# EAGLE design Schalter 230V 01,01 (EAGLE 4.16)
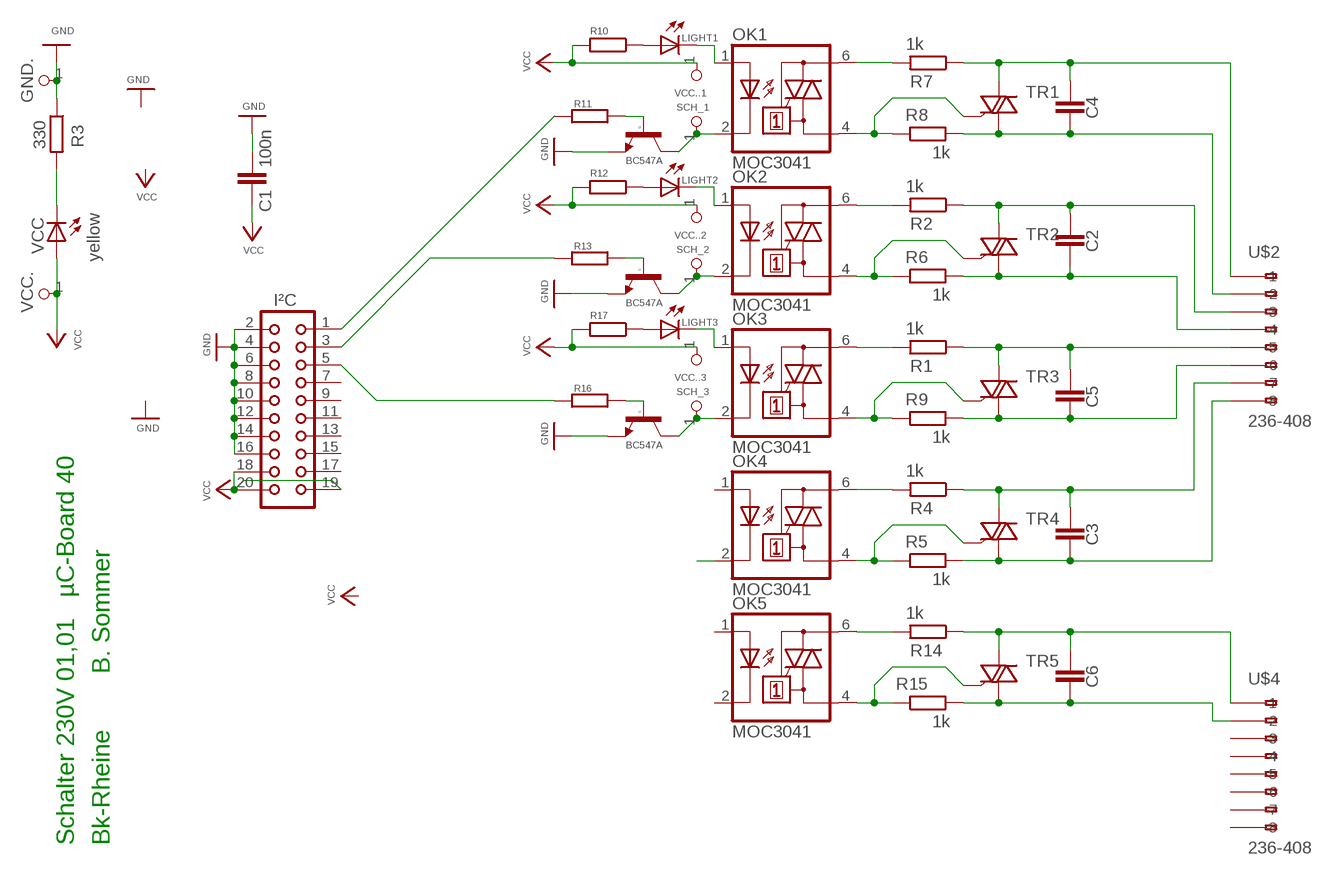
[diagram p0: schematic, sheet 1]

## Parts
C1  100n  C-EU025-030X050  [C025-030X050]
C2  C-EU075-052X106  [C075-052X106]
C3  C-EU075-052X106  [C075-052X106]
C4  C-EU075-052X106  [C075-052X106]
C5  C-EU075-052X106  [C075-052X106]
C6  C-EU075-052X106  [C075-052X106]
GND.  PINHD-1X1  [1X01]
I²C  CON20  [CON20]
LIGHT1  LED3MM  [LED3MM]
LIGHT2  LED3MM  [LED3MM]
LIGHT3  LED3MM  [LED3MM]
OK1  MOC3041  IL410  [DIL06]
OK2  MOC3041  IL410  [DIL06]
OK3  MOC3041  IL410  [DIL06]
OK4  MOC3041  IL410  [DIL06]
OK5  MOC3041  IL410  [DIL06]
Q1  BC547A  [TO92]
Q2  BC547A  [TO92]
Q3  BC547A  [TO92]
R1  1k  R-EU_0204/7  [0204/7]
R2  1k  R-EU_0204/7  [0204/7]
R3  330  R-EU_0204/7  [0204/7]
R4  1k  R-EU_0204/7  [0204/7]
R5  1k  R-EU_0204/7  [0204/7]
R6  1k  R-EU_0204/7  [0204/7]
R7  1k  R-EU_0204/7  [0204/7]
R8  1k  R-EU_0204/7  [0204/7]
R9  1k  R-EU_0204/7  [0204/7]
R10  R-EU_0204/7  [0204/7]
R11  R-EU_0204/7  [0204/7]
R12  R-EU_0204/7  [0204/7]
R13  R-EU_0204/7  [0204/7]
R14  1k  R-EU_0204/7  [0204/7]
R15  1k  R-EU_0204/7  [0204/7]
R16  R-EU_0204/7  [0204/7]
R17  R-EU_0204/7  [0204/7]
SCH_1  PINHD-1X1  [1X01]
SCH_2  PINHD-1X1  [1X01]
SCH_3  PINHD-1X1  [1X01]
TR1  BT138  [TO220XL]
TR2  BT138  [TO220XL]
TR3  BT138  [TO220XL]
TR4  BT138  [TO220XL]
TR5  BT138  [TO220XL]
U$2  236-408  [236-408]
U$4  236-408  [236-408]
VCC  yellow  LED3MM  [LED3MM]
VCC.  PINHD-1X1  [1X01]
VCC..1  PINHD-1X1  [1X01]
VCC..2  PINHD-1X1  [1X01]
VCC..3  PINHD-1X1  [1X01]

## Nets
GND: C1.2 GND..1 I²C.2 I²C.4 I²C.6 I²C.8 I²C.10 I²C.12 I²C.14 I²C.16 Q1.1(E) Q2.1(E) Q3.1(E) R3.1
N$1: R3.2 VCC.K(C)
N$2: LIGHT2.A R12.1
N$3: OK4.2(C)
N$4: LIGHT2.K(C) OK2.1(A)
N$5: OK2.2(C) Q1.3(C) SCH_2.1
N$6: Q1.2(B) R13.1
N$7: OK2.6(A2) R2.2
N$8: OK2.4(A1) R6.1 TR2.G
N$9: OK1.6(A2) R7.2
N$10: C2.1 R6.2 TR2.A1 U$2.A4(-4)
N$11: C2.2 R2.1 TR2.A2 U$2.A3(-3)
N$12: OK1.4(A1) R8.1 TR1.G
N$13: C4.1 R8.2 TR1.A1 U$2.A2(-2)
N$14: OK3.6(A2) R1.2
N$15: C4.2 R7.1 TR1.A2 U$2.A1(-1)
N$16: C5.2 R1.1 TR3.A2 U$2.A5(-5)
N$17: C5.1 R9.2 TR3.A1 U$2.A6(-6)
N$18: OK3.4(A1) R9.1 TR3.G
N$19: LIGHT1.K(C) OK1.1(A)
N$20: LIGHT1.A R10.1
N$21: OK1.2(C) Q2.3(C) SCH_1.1
N$22: Q2.2(B) R11.1
N$23: OK5.6(A2) R14.2
N$24: OK4.6(A2) R4.2
N$25: OK4.4(A1) R5.1 TR4.G
N$26: OK5.4(A1) R15.1 TR5.G
N$28: C6.2 R14.1 TR5.A2 U$4.A1(-1)
N$29: C6.1 R15.2 TR5.A1 U$4.A2(-2)
N$30: I²C.1 R11.2
N$31: I²C.3 R13.2
N$32: C3.2 R4.1 TR4.A2 U$2.A7(-7)
N$33: C3.1 R5.2 TR4.A1 U$2.A8(-8)
N$34: LIGHT3.A R17.1
N$35: LIGHT3.K(C) OK3.1(A)
N$37: Q3.2(B) R16.1
N$38: OK3.2(C) Q3.3(C) SCH_3.1
N$39: I²C.5 R16.2
VCC: C1.1 I²C.18 I²C.19 I²C.20 R10.2 R12.2 R17.2 VCC..1 VCC..1.1 VCC..2.1 VCC..3.1 VCC.A
Unconnected: I²C.7 I²C.9 I²C.11 I²C.13 I²C.15 I²C.17 OK4.1(A) OK5.1(A) OK5.2(C) U$2.B1(B-1) U$2.B2(B-2) U$2.B3(B-3) U$2.B4(B-4) U$2.B5(B-5) U$2.B6(B-6) U$2.B7(B-7) U$2.B8(B-8) U$4.A3(-3) U$4.A4(-4) U$4.A5(-5) U$4.A6(-6) U$4.A7(-7) U$4.A8(-8) U$4.B1(B-1) U$4.B2(B-2) U$4.B3(B-3) U$4.B4(B-4) U$4.B5(B-5) U$4.B6(B-6) U$4.B7(B-7) U$4.B8(B-8)

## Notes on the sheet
- Schalter 230V 01,01   µC-Board 40 | Bk-Rheine        B. Sommer

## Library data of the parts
C1-C6 = rcl:C-EU: CAPACITOR, European symbol
GND. SCH_1-SCH_3 VCC. VCC..1-VCC..3 = pinhead 02:PINHD-1X1: PIN HEADER
I²C = con-harting:CON20: CONNECTOR
LIGHT1-LIGHT3 VCC = led:LED: LED
OK1-OK5 = optocoupler:IL410: SIEMENS OPTO COUPLER
Q1-Q3 = transistor-npn:BC547*: NPN Transistor
R1-R17 = rcl:R-EU_: RESISTOR, European symbol
TR1-TR5 = triac:BT138
U$2 U$4 = con-wago255:236-408

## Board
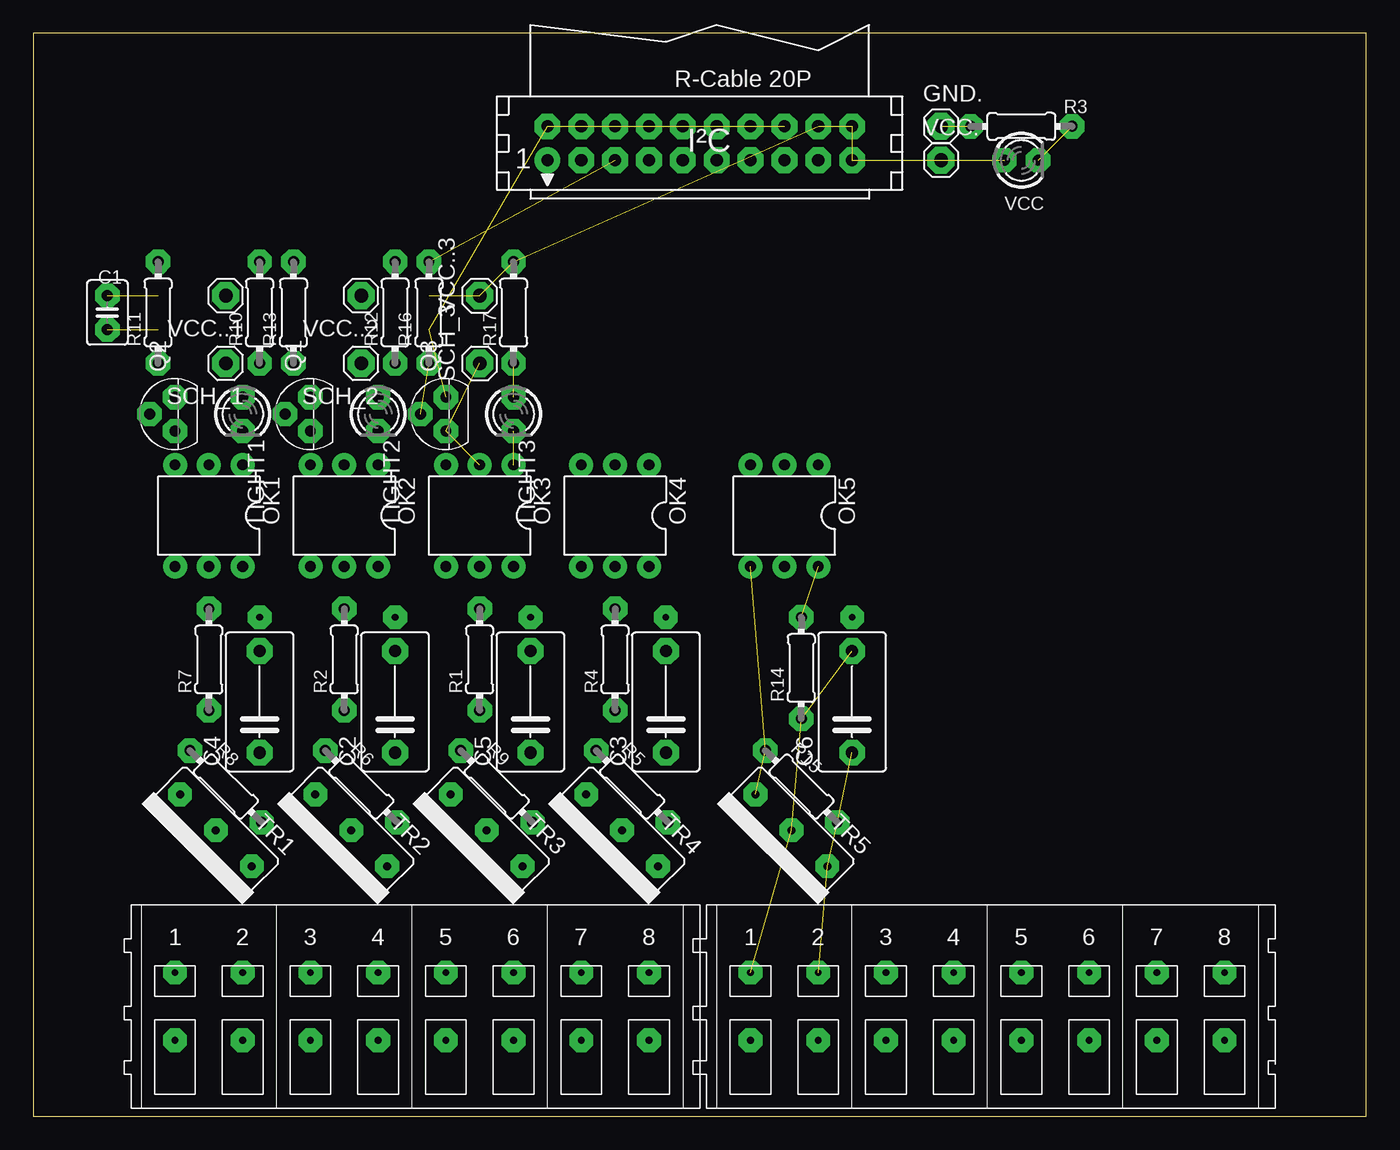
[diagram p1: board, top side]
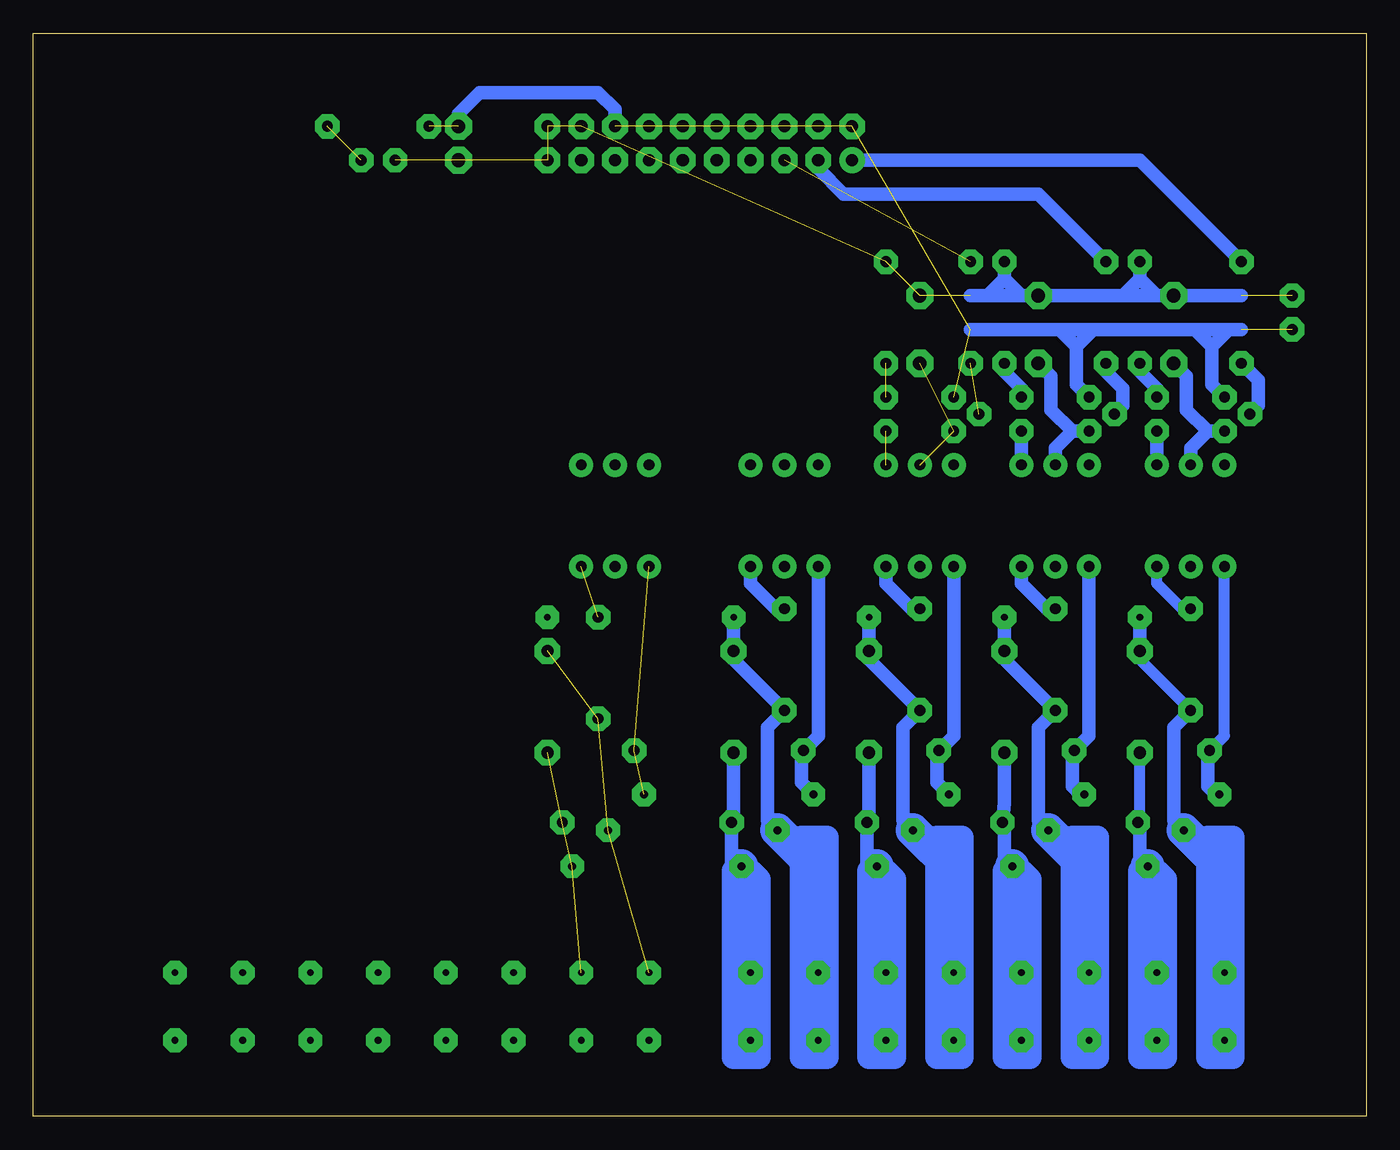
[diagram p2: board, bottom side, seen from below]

Size 100 x 81.27 mm. Coordinates in mm from the lower left corner, seen from the top.
Outline: 0,0 100,0 100,81.27 0,81.27 0,0
Copper layers (1*16): Top 0.035mm / dielectric 1.5mm / Bottom 0.035mm
Design rules "sommer_01_Ätzen": minimum track width 24mil, minimum drill 5mil, track to track 27mil, track to pad 27mil, pad to pad 10mil, via to via 10mil, smd to smd 8mil, copper to edge 0mil, drill to drill 25mil, minimum pad ring 20mil, minimum via ring 20mil, stop-mask expansion 4mil, vias tented up to drill 0mil, thermal gap 20mil

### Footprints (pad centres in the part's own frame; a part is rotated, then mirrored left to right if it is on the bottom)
C025-030X050 = drill 0.813 octagon: 1 -1.27,0; 2 1.27,0
C075-052X106 = drill 0.914 octagon: 1 -3.81,0; 2 3.81,0
1X01 = drill 1.016 octagon: 1 0,0
CON20 = drill 0.914 round: 1 -11.43,-1.27 | drill 0.914 octagon: 2 -11.43,1.27; 3 -8.89,-1.27; 4 -8.89,1.27; 5 -6.35,-1.27; 6 -6.35,1.27; 7 -3.81,-1.27; 8 -3.81,1.27; 9 -1.27,-1.27; 10 -1.27,1.27; 11 1.27,-1.27; 12 1.27,1.27; 13 3.81,-1.27; 14 3.81,1.27; 15 6.35,-1.27; 16 6.35,1.27; 17 8.89,-1.27; 18 8.89,1.27; 19 11.43,-1.27; 20 11.43,1.27
LED3MM = drill 0.813 octagon: A -1.27,0; K 1.27,0
DIL06 = drill 0.813 long: 1 -2.54,-3.81; 2 0,-3.81; 3 2.54,-3.81; 4 2.54,3.81; 5 0,3.81; 6 -2.54,3.81
TO92 = drill 0.813 octagon: 1 1.27,0; 2 0,1.905; 3 -1.27,0
0204/7 = drill 0.813 octagon: 1 -3.81,0; 2 3.81,0
TO220XL = drill 0.6 pad 1.778 octagon: A1 -3.81,-2.54; A2 0,-2.54; G 3.81,-2.54
236-408 = drill 0.5 pad 1.778 octagon: A1 -17.78,2.54; A2 -12.7,2.54; A3 -7.62,2.54; A4 -2.54,2.54; A5 2.54,2.54; A6 7.62,2.54; A7 12.7,2.54; A8 17.78,2.54; B1 -17.78,-2.54; B2 -12.7,-2.54; B3 -7.62,-2.54; B4 -2.54,-2.54; B5 2.54,-2.54; B6 7.62,-2.54; B7 12.7,-2.54; B8 17.78,-2.54

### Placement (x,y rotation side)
C1  5.55,60.32 270 top
C2  27.14,31.11 90 top
C3  47.46,31.11 90 top
C4  16.98,31.11 90 top
C5  37.3,31.11 90 top
C6  61.43,31.11 90 top
GND.  68.1,74.29 0 top
I²C  50,73.02 0 top
LIGHT1  15.71,52.7 270 top
LIGHT2  25.87,52.7 270 top
LIGHT3  36.03,52.7 270 top
OK1  13.17,45.08 180 top
OK2  23.33,45.08 180 top
OK3  33.49,45.08 180 top
OK4  43.65,45.08 180 top
OK5  56.35,45.08 180 top
Q1  20.79,52.7 90 top
Q2  10.63,52.7 90 top
Q3  30.95,52.7 90 top
R1  33.49,34.29 90 top
R2  23.33,34.29 90 top
R3  74.13,74.29 0 top
R4  43.65,34.29 90 top
R5  44.92,24.76 315 top
R6  24.6,24.76 315 top
R7  13.17,34.29 90 top
R8  14.44,24.76 315 top
R9  34.76,24.76 315 top
R10  16.98,60.32 90 top
R11  9.36,60.32 90 top
R12  27.14,60.32 90 top
R13  19.52,60.32 90 top
R14  57.62,33.65 90 top
R15  57.62,24.76 315 top
R16  29.68,60.32 90 top
R17  36.03,60.32 90 top
SCH_1  14.44,56.51 180 top
SCH_2  24.6,56.51 180 top
SCH_3  33.49,56.51 90 top
TR1  11.9,19.68 135 top
TR2  22.06,19.68 135 top
TR3  32.22,19.68 135 top
TR4  42.38,19.68 135 top
TR5  55.08,19.68 135 top
U$2  28.41,8.25 0 top
U$4  71.59,8.25 0 top
VCC  74.13,71.75 0 top
VCC.  68.1,71.75 0 top
VCC..1  14.44,61.59 180 top
VCC..2  24.6,61.59 180 top
VCC..3  33.49,61.59 90 top

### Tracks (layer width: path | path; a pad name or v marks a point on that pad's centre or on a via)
GND  (11 unrouted)
  Bottom 1.016: Q2.1 11.58,54.92 11.58,57.78 | 11.58,57.78 12.85,59.05 | 12.85,59.05 10.31,59.05 | 11.58,57.78 10.31,59.05 | 10.31,59.05 9.36,59.05 | Q1.1 21.74,54.92 21.74,57.78 | 20.47,59.05 21.74,57.78 | 12.85,59.05 20.47,59.05 | 20.47,59.05 23.01,59.05 | 23.01,59.05 29.68,59.05 | 21.74,57.78 23.01,59.05 | GND..1 68.1,75.24 66.51,76.83 57.62,76.83 56.35,75.56 I²C.16
N$1  (1 unrouted)
N$2
  Bottom 1.016: R12.1 27.14,55.88 25.87,54.61 LIGHT2.A
N$4
  Bottom 1.016: OK2.1 LIGHT2.K
N$5
  Bottom 1.016: OK2.2 23.33,50.16 22.06,51.43 | Q1.3 22.06,51.43 | SCH_2.1 23.65,55.56 23.65,53.02 22.06,51.43
N$6
  Bottom 1.016: Q1.2 18.25,53.34 18.25,54.61 19.52,55.88 R13.1
N$7
  Bottom 1.016: OK2.6 25.87,40 23.96,38.1 R2.2
N$8
  Bottom 1.016: OK2.4 20.79,28.57 R6.1 22.06,27.3 22.06,24.76 21.47,24.17 TR2.G
N$9
  Bottom 0.813: OK1.6 15.71,40 13.81,38.1 R7.2
N$10
  Bottom 1.016: C2.1 27.14,23.49 R6.2 27.14,21.91 27.14,19.37 TR2.A1
  Bottom 1.778: 25.87,12.06 27.14,12.06 27.14,10.79 | 27.14,10.79 27.14,4.44 25.87,4.44 | 25.87,4.44 25.23,4.44 25.23,17.77 26.5,19.04 | 27.14,10.79 27.14,18.41 | 27.14,10.79 U$2.A4 | 25.87,4.44 25.87,17.14
  Bottom 2.54: TR2.A1 26.55,12.74 25.87,12.06
N$11  (via drill 0.5 pad 1.78)
  Bottom 1.016: TR2.A2 24.6,22.22 24.6,29.2 R2.1 27.14,34.29 C2.2 v27.14,37.46
  Bottom 1.778: 22.06,4.44 22.06,12.06 20.79,12.06 U$2.A3 | 20.79,4.44 20.15,4.44 20.15,20.95 22.06,20.95 22.06,4.44 | 20.79,4.44 22.06,4.44 | 20.79,4.44 20.79,18.41
  Bottom 2.54: TR2.A2 20.79,18.41 20.79,12.06
N$12
  Bottom 0.813: R8.1 11.9,27.3 10.63,28.57 OK1.4
  Bottom 1.016: 11.64,27.04 11.9,27.3 11.9,24.76 11.31,24.17 TR1.G
N$13
  Bottom 0.813: R8.2 16.98,22.22 C4.1
  Bottom 1.016: TR1.A1 16.98,19.37 16.98,21.91 R8.2
  Bottom 1.778: 15.71,12.06 16.98,12.06 16.98,10.79 | 16.98,10.79 16.98,4.44 15.71,4.44 | 15.71,4.44 15.08,4.44 15.08,17.77 16.34,19.04 16.98,18.41 16.98,10.79 | 16.98,10.79 U$2.A2 | 15.71,4.44 15.71,14.6
  Bottom 2.54: TR1.A1 16.39,12.74 15.71,12.06
N$14
  Bottom 1.016: OK3.6 36.03,40 34.12,38.1 R1.2
N$15  (via drill 0.5 pad 1.78)
  Bottom 0.813: C4.2 16.98,34.29 R7.1
  Bottom 1.016: TR1.A2 14.44,22.22 14.44,29.2 R7.1 | C4.2 v16.98,37.46
  Bottom 1.778: 11.9,12.06 10.63,12.06 U$2.A1 | 11.9,12.06 11.9,19.68 11.9,20.95 10,20.95 10,4.44 10.63,4.44 | 10.63,4.44 11.9,4.44 11.9,12.06 | 10.63,4.44 10.63,18.41
  Bottom 2.54: TR1.A2 11.9,19.68 10.63,18.41 10.63,12.06
N$16  (via drill 0.5 pad 1.78)
  Bottom 1.016: TR3.A2 34.76,22.22 34.76,29.2 R1.1 37.3,34.29 C5.2 v37.3,37.46
  Bottom 1.778: 32.22,4.44 32.22,12.06 30.95,12.06 U$2.A5 | 30.95,4.44 30.31,4.44 30.31,20.95 32.22,20.95 32.22,4.44 | 30.95,4.44 32.22,4.44 | 30.95,4.44 30.95,18.41
  Bottom 2.54: TR3.A2 30.95,18.41 30.95,12.06
N$17
  Bottom 1.016: TR3.A1 36.71,19.09 37.45,19.2 R9.2 37.3,22.22 C5.1
  Bottom 1.778: 37.3,4.44 37.3,12.06 36.03,12.06 U$2.A6 | 36.03,4.44 35.39,4.44 35.39,17.77 36.66,19.04 37.3,18.41 37.3,4.44 | 36.03,4.44 37.3,4.44 | 36.03,4.44 36.03,15.87
  Bottom 2.54: TR3.A1 36.71,12.74 36.03,12.06
N$18
  Bottom 1.016: TR3.G 32.22,25.07 32.22,27.3 R9.1 30.95,28.57 OK3.4
N$19
  Bottom 1.016: OK1.1 LIGHT1.K
N$20
  Bottom 1.016: R10.1 16.98,55.88 15.71,54.61 LIGHT1.A
N$21
  Bottom 1.016: SCH_1.1 13.49,55.56 13.49,53.02 11.9,51.43 | Q2.3 11.9,51.43 | 11.9,51.43 13.17,50.16 OK1.2
N$22
  Bottom 1.016: Q2.2 8.09,53.34 8.09,55.24 R11.1
N$23  (1 unrouted)
N$24
  Bottom 1.016: OK4.6 46.19,40 44.28,38.1 R4.2
N$25
  Bottom 1.016: TR4.G 42.38,25.07 42.38,27.3 R5.1 41.11,28.57 OK4.4
N$26  (2 unrouted)
N$27  (via drill 0.5 pad 1.78)
  other vias: 61.43,37.46
N$28  (3 unrouted)
N$29  (3 unrouted)
N$30
  Bottom 1.016: R11.2 16.98,71.75 I²C.1
N$31
  Bottom 1.016: R13.2 24.6,69.21 39.2,69.21 41.11,71.11 I²C.3
N$32  (via drill 0.5 pad 1.78)
  Bottom 1.016: TR4.A2 44.92,22.22 44.92,29.2 R4.1 47.46,34.29 C3.2 v47.46,37.46
  Bottom 1.778: 42.38,4.44 42.38,12.06 41.11,12.06 U$2.A7 | 41.11,4.44 40.48,4.44 40.48,20.95 42.38,20.95 41.11,19.68 42.38,19.68 42.38,4.44 | 41.11,4.44 42.38,4.44 | 41.11,4.44 41.11,18.41
  Bottom 2.54: TR4.A2 42.38,19.68 41.11,18.41 41.11,12.06
N$33
  Bottom 1.016: TR4.A1 46.87,19.09 47.61,19.2 R5.2 47.46,22.22 C3.1
  Bottom 1.778: 47.46,4.44 47.46,12.06 46.19,12.06 U$2.A8 | 46.19,4.44 47.46,4.44 | 46.19,4.44 45.55,4.44 45.55,17.77 46.82,19.04 47.46,18.41 47.46,4.44 | 46.19,4.44 46.19,14.6
  Bottom 2.54: TR4.A1 46.87,12.74 46.19,12.06
N$34  (1 unrouted)
N$35  (1 unrouted)
N$37  (1 unrouted)
N$38  (2 unrouted)
N$39  (1 unrouted)
VCC  (8 unrouted)
  Bottom 1.016: VCC..1.1 15.71,61.59 16.98,62.86 | 16.98,62.86 R10.2 | 9.36,61.59 VCC..1.1 | 27.14,62.86 R12.2 | 25.87,61.59 27.14,62.86 | 25.87,61.59 VCC..2.1 18.25,61.59 | VCC..1.1 18.25,61.59 | 18.25,61.59 16.98,62.86 | 25.87,61.59 28.41,61.59 | 27.14,62.86 28.41,61.59 | 28.41,61.59 29.68,61.59

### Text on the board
Bottom: B. Sommer | BK-Rheine 07-08 | GOOD LUCK ! | I²C - ROOM & LIGHT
